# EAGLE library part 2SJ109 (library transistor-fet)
DUAL FIELD EFFECT TRANSISTOR SILICON MONOLITHIC P CHANNEL JUNCTION TYPE Source:http://www.datasheetcatalog.org/datasheets/270/201785_DS.pdf
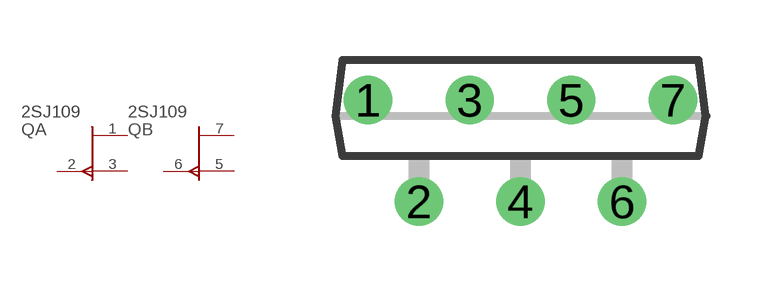
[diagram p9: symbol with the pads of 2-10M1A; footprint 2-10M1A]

Designator prefix Q; gates A=JFET_P B=JFET_P

## 2SJ109  [2-10M1A]
1  A:D  pas
2  A:G  pas
3  A:S  pas
5  B:S  pas
6  B:G  pas
7  B:D  pas

## Footprint 2-10M1A (pad centres in mm)
Single In Line 2-10M1A Source: http://pdf1.alldatasheet.com/datasheet-pdf/view/30769/TOSHIBA/2SK389.html
drill 0.7 pad 1.2 round: 1 -3.81,0; 2 -2.54,-2.54; 3 -1.27,0; 4 0,-2.54; 5 1.27,0; 6 2.54,-2.54; 7 3.81,0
